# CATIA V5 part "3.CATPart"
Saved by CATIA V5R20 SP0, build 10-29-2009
Part number: 3
Bounding box of the stored display mesh (mm): x -37.6 to 37.6, y -37.6 to 37.6, z 8.682 to 37.611
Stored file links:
  E:\Ehsan\Amoozesh\CATIA\CATIA Course\Advanced\Videos\Session-19\3.CATPart
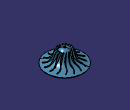
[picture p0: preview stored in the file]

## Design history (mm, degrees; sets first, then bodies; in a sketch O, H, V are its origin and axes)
AxisSystem1: origin (0, 0, 0), X (1, 0, 0), Y (0, 1, 0), Z (0, 0, 1)
Set1 "Surfaces"
  Revol1: Element1 Sketch1, Angle1 360, Line Sketch1.V
  Sweep1: type Segment, GuideCrv Project1, GuideSurf Revol1, Length1 0, Length2 2, Length1 0, LengthEnd2 5, Angle 80, AngleEnd 70
  CircPattern1: of Sweep1, instances 16, angular step 22.5 {= 360.0*1 deg/CircPattern1.AngularNumber}, axis from edge [ZX plane of AxisSystem1 | YZ plane of AxisSystem1]
Set2 "Sketches"
  Sketch1 on YZ plane of AxisSystem1, origin (0, 0, 0), H (0, 1, 0), V (0, 0, 1)
    spline S1 through (37.4137, 8.6819) (26.2516, 11.6757) (15.2962, 18.8607) (11.3688, 27.6424) (7.4414, 34.0291) (1.8603, 36.6237)
  Sketch2 on XY plane of AxisSystem1, origin (0, 0, 0), H (1, 0, 0), V (0, 1, 0)
    spline S1 through (30.7991, -10.4782) (28.9387, -8.6819) (25.4248, -6.0873) (20.6705, -4.8898) (13.8493, -3.6923) (9.095, 0)
    point P1 (9.095, 0)
    coincidence: P1 H
Set3 "Curves"
  Project1: ToProject Sketch2, Support Revol1, Direction Sketch1.V
Body1 (main body)
  ThickSurface1: Surface Revol1, TopOffset 1, BotOffset 0
  ThickSurface2: Surface CircPattern1, TopOffset 1, BotOffset 0
  ThickSurface3: Surface Sweep1, TopOffset 1, BotOffset 0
